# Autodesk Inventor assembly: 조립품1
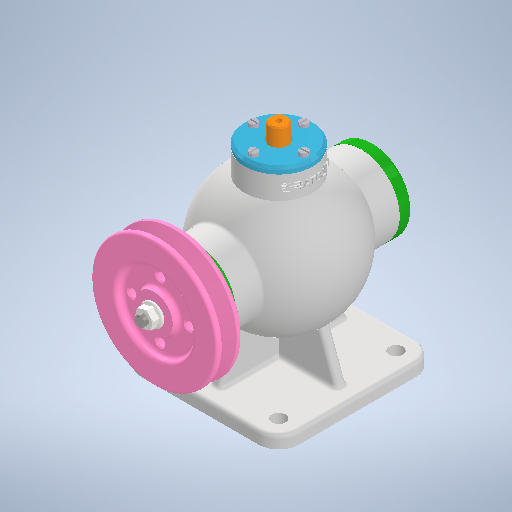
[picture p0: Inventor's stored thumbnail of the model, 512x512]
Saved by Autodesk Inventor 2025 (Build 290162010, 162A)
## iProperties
Created: 2024-07
Part Number: 조립품1
Document SubType Name: Assembly
Designer: 학생
Author: 학생
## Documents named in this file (14)
- C:\Users\학생\Desktop\740708v1002\740708v1002\조립품1.iam
- C:\Users\학생\Desktop\740708v1002\740708v1002\본체.ipt
- C:\Users\학생\Desktop\740708v1002\740708v1002\V-벨트풀리\V-벨트풀리.ipt
- C:\Users\학생\Desktop\740708v1002\740708v1002\너트 M8\너트 M8.ipt
- C:\Users\학생\Desktop\740708v1002\740708v1002\베어링- 6202\베어링- 6202.ipt
- C:\Users\학생\Desktop\740708v1002\740708v1002\볼트 M4 x 12\볼트 M4 x 12.ipt
- C:\Users\학생\Desktop\740708v1002\740708v1002\볼트 M4 x 16\볼트 M4 x 16.ipt
- C:\Users\학생\Desktop\740708v1002\740708v1002\상부커버\상부커버.ipt
- C:\Users\학생\Desktop\740708v1002\740708v1002\슬라이드\슬라이드.ipt
- C:\Users\학생\Desktop\740708v1002\740708v1002\앞커버\앞커버.ipt
- C:\Users\학생\Desktop\740708v1002\740708v1002\오일실 15 30 7\오일실 15 30 7.ipt
- C:\Users\학생\Desktop\740708v1002\740708v1002\칼라\칼라.ipt
- C:\Users\학생\Desktop\740708v1002\740708v1002\키 4 x 4 x 12\키 4 x 4 x 12.ipt
- C:\Users\학생\Desktop\740708v1002\740708v1002\편심축\편심축.ipt
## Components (1 placed, 1 different names)
1. V-벨트풀리:1 — 각도:5
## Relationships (1: Angle 1)
- 각도:5 [Angle]: V-벨트풀리:1
